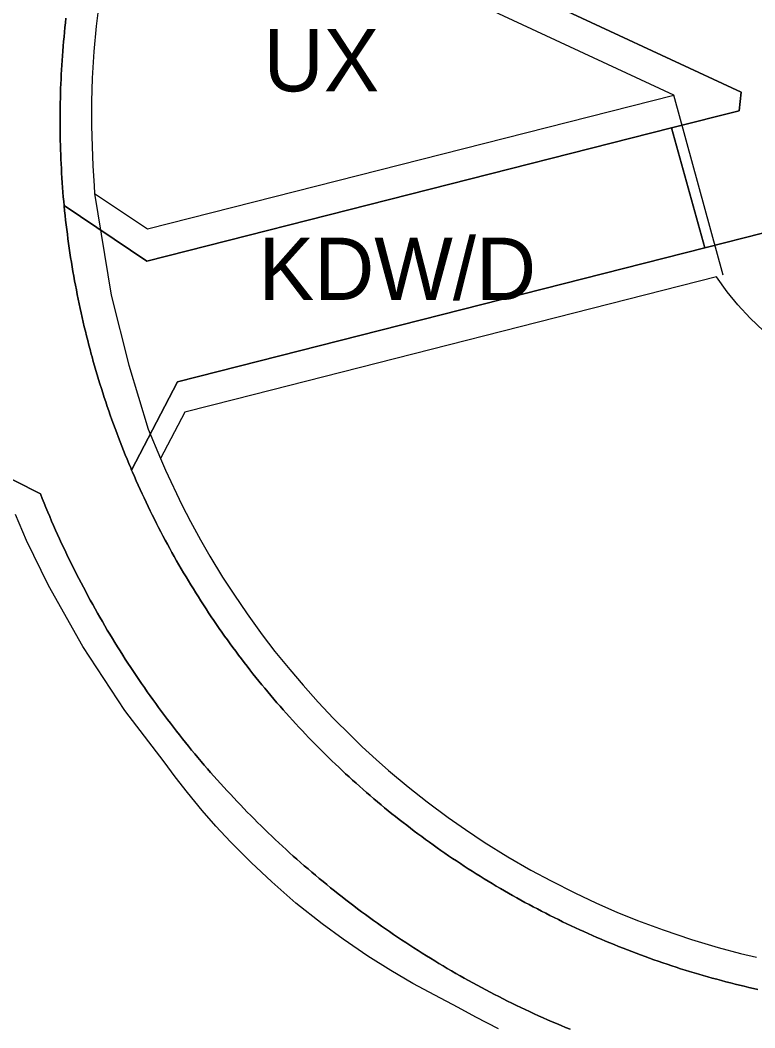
# Model space of a CAD drawing. Extents: x -297746 to -295403, y 27112 to 28877.
# Drawn here: x -297178.2 to -297060.2, y 27583.6 to 27745.5 of the extents above; entities that cross this region are included whole.
import ezdxf

# ---------------------------------------------------------------- set-up
doc = ezdxf.new("R2010")
doc.units = 0
for name, color, linetype in [('linie_rozgraniczajace', 7, 'Continuous'), ('linie_zabudowy_obowiazujace', 7, 'Continuous'), ('oznaczenia_przeznaczen', 7, 'Continuous')]:
    doc.layers.add(name, color=color, linetype=linetype)

msp = doc.modelspace()

# ---------------------------------------------------------------- linework, layer by layer
at = {"layer": 'linie_rozgraniczajace'}
for points in [[(-297152.791, 27775.987), (-297062.466, 27733.921), (-297062.777, 27730.939), (-297073.62, 27728.183), (-297157.907, 27706.762), (-297171.185, 27715.692), (-297171.248, 27716.366), (-297171.315, 27717.119), (-297171.378, 27717.873), (-297171.436, 27718.627), (-297171.491, 27719.381), (-297171.542, 27720.136), (-297171.589, 27720.891), (-297171.631, 27721.646), (-297171.67, 27722.401), (-297171.705, 27723.157), (-297171.736, 27723.912), (-297171.763, 27724.668), (-297171.786, 27725.424), (-297171.804, 27726.18), (-297171.819, 27726.936), (-297171.83, 27727.693), (-297171.837, 27728.449), (-297171.84, 27729.205), (-297171.838, 27729.962), (-297171.833, 27730.718), (-297171.824, 27731.474), (-297171.811, 27732.23), (-297171.794, 27732.986), (-297171.773, 27733.742), (-297171.747, 27734.498), (-297171.718, 27735.254), (-297171.685, 27736.01), (-297171.648, 27736.765), (-297171.607, 27737.52), (-297171.562, 27738.275), (-297171.513, 27739.03), (-297171.459, 27739.784), (-297171.402, 27740.538), (-297171.341, 27741.292), (-297171.276, 27742.046), (-297171.207, 27742.799), (-297171.134, 27743.552), (-297171.057, 27744.304), (-297170.976, 27745.056), (-297170.891, 27745.807)], [(-297059.011, 27711.26), (-297068.251, 27708.911), (-297073.62, 27728.183), (-297062.777, 27730.939), (-297062.466, 27733.921), (-297152.791, 27775.987)], [(-297170.891, 27745.807), (-297170.976, 27745.056), (-297171.057, 27744.304), (-297171.134, 27743.552), (-297171.207, 27742.799), (-297171.276, 27742.046), (-297171.341, 27741.292), (-297171.402, 27740.538), (-297171.459, 27739.784), (-297171.513, 27739.03), (-297171.562, 27738.275), (-297171.607, 27737.52), (-297171.648, 27736.765), (-297171.685, 27736.01), (-297171.718, 27735.254), (-297171.747, 27734.498), (-297171.773, 27733.742), (-297171.794, 27732.986), (-297171.811, 27732.23), (-297171.824, 27731.474), (-297171.833, 27730.718), (-297171.838, 27729.962), (-297171.84, 27729.205), (-297171.837, 27728.449), (-297171.83, 27727.693), (-297171.819, 27726.936), (-297171.804, 27726.18), (-297171.786, 27725.424), (-297171.763, 27724.668), (-297171.736, 27723.912), (-297171.705, 27723.157), (-297171.67, 27722.401), (-297171.631, 27721.646), (-297171.589, 27720.891), (-297171.542, 27720.136), (-297171.491, 27719.381), (-297171.436, 27718.627), (-297171.378, 27717.873), (-297171.315, 27717.119), (-297171.248, 27716.366), (-297171.185, 27715.692), (-297171.177, 27715.613), (-297171.103, 27714.86), (-297171.024, 27714.108), (-297170.941, 27713.356), (-297170.855, 27712.605), (-297170.764, 27711.854), (-297170.669, 27711.104), (-297170.571, 27710.354), (-297170.468, 27709.605), (-297170.362, 27708.856), (-297170.251, 27708.108), (-297170.137, 27707.36), (-297170.019, 27706.613), (-297169.896, 27705.867), (-297169.77, 27705.121), (-297169.64, 27704.376), (-297169.506, 27703.632), (-297169.368, 27702.888), (-297169.226, 27702.145), (-297169.08, 27701.403), (-297168.93, 27700.662), (-297168.776, 27699.921), (-297168.619, 27699.182), (-297168.457, 27698.443), (-297168.292, 27697.705), (-297168.122, 27696.968), (-297167.949, 27696.231), (-297167.772, 27695.496), (-297167.591, 27694.762), (-297167.406, 27694.029)], [(-297152.753, 27657.985), (-297153.129, 27658.642), (-297153.501, 27659.3), (-297153.87, 27659.96), (-297154.235, 27660.622), (-297154.597, 27661.287), (-297154.955, 27661.953), (-297155.31, 27662.621), (-297155.661, 27663.29), (-297156.009, 27663.962), (-297156.353, 27664.636), (-297156.693, 27665.311), (-297157.03, 27665.988), (-297157.364, 27666.667), (-297157.693, 27667.347), (-297158.02, 27668.03), (-297158.342, 27668.714), (-297158.661, 27669.4), (-297158.976, 27670.087), (-297159.288, 27670.776), (-297159.596, 27671.467), (-297159.901, 27672.159), (-297160.201, 27672.853), (-297160.351, 27673.202), (-297152.966, 27687.382), (-297068.251, 27708.911), (-297059.011, 27711.26)], [(-297167.406, 27694.029), (-297167.217, 27693.296), (-297167.024, 27692.565), (-297166.828, 27691.835), (-297166.707, 27691.393), (-297166.504, 27690.665), (-297166.298, 27689.937), (-297166.087, 27689.211), (-297165.873, 27688.485), (-297165.655, 27687.761), (-297165.433, 27687.038), (-297165.207, 27686.316), (-297164.978, 27685.596), (-297164.744, 27684.876), (-297164.507, 27684.158), (-297164.266, 27683.441), (-297164.022, 27682.726), (-297163.773, 27682.011), (-297163.521, 27681.298), (-297163.265, 27680.587), (-297163.005, 27679.877), (-297162.741, 27679.168), (-297162.474, 27678.46), (-297162.203, 27677.754), (-297161.928, 27677.05), (-297161.649, 27676.346), (-297161.367, 27675.645), (-297161.081, 27674.945), (-297160.792, 27674.246), (-297160.498, 27673.549), (-297160.351, 27673.202), (-297160.201, 27672.853), (-297159.901, 27672.159), (-297159.596, 27671.467), (-297159.288, 27670.776), (-297158.976, 27670.087), (-297158.661, 27669.4), (-297158.342, 27668.714), (-297158.02, 27668.03), (-297157.693, 27667.347), (-297157.364, 27666.667), (-297157.03, 27665.988), (-297156.693, 27665.311), (-297156.353, 27664.636), (-297156.009, 27663.962), (-297155.661, 27663.29), (-297155.31, 27662.621), (-297154.955, 27661.953), (-297154.597, 27661.287), (-297154.235, 27660.622), (-297153.87, 27659.96), (-297153.501, 27659.3), (-297153.129, 27658.642), (-297152.753, 27657.985), (-297152.374, 27657.331), (-297151.991, 27656.679), (-297151.605, 27656.028), (-297151.215, 27655.38), (-297150.822, 27654.734), (-297150.426, 27654.09), (-297150.026, 27653.448), (-297149.623, 27652.808), (-297149.216, 27652.17), (-297148.806, 27651.535), (-297148.393, 27650.901), (-297147.976, 27650.27), (-297147.556, 27649.641), (-297147.133, 27649.014), (-297146.707, 27648.39), (-297146.277, 27647.767), (-297145.843, 27647.147), (-297145.407, 27646.53), (-297144.967, 27645.914), (-297144.524, 27645.301), (-297144.078, 27644.691), (-297143.629, 27644.083), (-297143.176, 27643.477), (-297142.72, 27642.873), (-297142.261, 27642.272), (-297141.799, 27641.673), (-297141.334, 27641.077), (-297140.865, 27640.483), (-297140.394, 27639.892), (-297139.919, 27639.303), (-297139.441, 27638.717), (-297138.96, 27638.134), (-297138.476, 27637.552), (-297137.989, 27636.974), (-297137.499, 27636.398), (-297137.006, 27635.824), (-297136.509, 27635.254), (-297136.01, 27634.686), (-297135.508, 27634.12), (-297135.003, 27633.557), (-297134.495, 27632.997), (-297133.983, 27632.44), (-297133.469, 27631.885), (-297132.952, 27631.333), (-297132.432, 27630.784), (-297131.91, 27630.237)], [(-297130.211, 27607.587), (-297130.815, 27608.092), (-297131.415, 27608.6), (-297132.014, 27609.111), (-297132.609, 27609.625), (-297133.202, 27610.142), (-297133.792, 27610.662), (-297134.38, 27611.186), (-297134.965, 27611.712), (-297135.547, 27612.241), (-297136.127, 27612.773), (-297136.704, 27613.308), (-297137.278, 27613.845), (-297137.849, 27614.386), (-297138.418, 27614.93), (-297138.984, 27615.476), (-297139.547, 27616.026), (-297140.107, 27616.578), (-297140.665, 27617.133), (-297141.219, 27617.691), (-297141.771, 27618.252), (-297142.32, 27618.815), (-297142.866, 27619.382), (-297143.41, 27619.951), (-297143.95, 27620.523), (-297144.487, 27621.097), (-297145.022, 27621.675), (-297145.553, 27622.255), (-297146.082, 27622.837), (-297146.607, 27623.423), (-297147.13, 27624.011), (-297147.65, 27624.602), (-297148.166, 27625.195), (-297148.68, 27625.791), (-297149.19, 27626.39), (-297149.698, 27626.991), (-297150.202, 27627.594), (-297150.704, 27628.201), (-297151.202, 27628.81), (-297151.697, 27629.421), (-297152.189, 27630.035), (-297152.678, 27630.651), (-297153.164, 27631.27), (-297153.646, 27631.891), (-297154.126, 27632.515), (-297154.602, 27633.141), (-297155.075, 27633.77), (-297155.545, 27634.401), (-297156.012, 27635.034), (-297156.475, 27635.67), (-297156.935, 27636.308), (-297157.392, 27636.948), (-297157.846, 27637.591), (-297158.296, 27638.236), (-297158.744, 27638.884), (-297159.187, 27639.533), (-297159.628, 27640.185), (-297160.065, 27640.839), (-297160.499, 27641.495), (-297160.93, 27642.154), (-297161.357, 27642.814), (-297161.781, 27643.477), (-297162.201, 27644.142), (-297162.618, 27644.809), (-297163.032, 27645.478), (-297163.442, 27646.15), (-297163.849, 27646.823), (-297164.252, 27647.499), (-297164.652, 27648.176), (-297165.049, 27648.856), (-297165.442, 27649.537), (-297165.831, 27650.221), (-297166.218, 27650.906), (-297166.6, 27651.593), (-297166.979, 27652.283), (-297167.355, 27652.974), (-297167.727, 27653.667), (-297168.096, 27654.362), (-297168.461, 27655.059), (-297168.822, 27655.758), (-297169.18, 27656.459), (-297169.534, 27657.161), (-297169.885, 27657.865), (-297170.232, 27658.571), (-297170.576, 27659.279), (-297170.916, 27659.988), (-297171.252, 27660.7), (-297171.585, 27661.413), (-297171.914, 27662.127), (-297172.24, 27662.843), (-297172.561, 27663.561), (-297172.88, 27664.281), (-297173.194, 27665.002), (-297173.505, 27665.725), (-297173.812, 27666.449), (-297174.116, 27667.175), (-297174.416, 27667.902), (-297174.712, 27668.631), (-297175.004, 27669.361), (-297191.301, 27677.639)], [(-297191.301, 27677.639), (-297175.004, 27669.361), (-297174.712, 27668.631), (-297174.416, 27667.902), (-297174.116, 27667.175), (-297173.812, 27666.449), (-297173.505, 27665.725), (-297173.194, 27665.002), (-297172.88, 27664.281), (-297172.561, 27663.561), (-297172.24, 27662.843), (-297171.914, 27662.127), (-297171.585, 27661.413), (-297171.252, 27660.7), (-297170.916, 27659.988), (-297170.576, 27659.279), (-297170.232, 27658.571), (-297169.885, 27657.865), (-297169.534, 27657.161), (-297169.18, 27656.459), (-297168.822, 27655.758), (-297168.461, 27655.059), (-297168.096, 27654.362), (-297167.727, 27653.667), (-297167.355, 27652.974), (-297166.979, 27652.283), (-297166.6, 27651.593), (-297166.218, 27650.906), (-297165.831, 27650.221), (-297165.442, 27649.537), (-297165.049, 27648.856), (-297164.652, 27648.176), (-297164.252, 27647.499), (-297163.849, 27646.823), (-297163.442, 27646.15), (-297163.032, 27645.478), (-297162.618, 27644.809), (-297162.201, 27644.142), (-297161.781, 27643.477), (-297161.357, 27642.814), (-297160.93, 27642.154), (-297160.499, 27641.495), (-297160.065, 27640.839), (-297159.628, 27640.185), (-297159.187, 27639.533), (-297158.744, 27638.884), (-297158.296, 27638.236), (-297157.846, 27637.591), (-297157.392, 27636.948), (-297156.935, 27636.308), (-297156.475, 27635.67), (-297156.012, 27635.034), (-297155.545, 27634.401), (-297155.075, 27633.77), (-297154.602, 27633.141), (-297154.126, 27632.515), (-297153.646, 27631.891), (-297153.164, 27631.27), (-297152.678, 27630.651), (-297152.189, 27630.035), (-297151.697, 27629.421), (-297151.202, 27628.81), (-297150.704, 27628.201), (-297150.202, 27627.594), (-297149.698, 27626.991), (-297149.19, 27626.39), (-297148.68, 27625.791), (-297148.166, 27625.195), (-297147.65, 27624.602), (-297147.13, 27624.011), (-297146.607, 27623.423), (-297146.082, 27622.837), (-297145.553, 27622.255), (-297145.022, 27621.675), (-297144.487, 27621.097), (-297143.95, 27620.523), (-297143.41, 27619.951), (-297142.866, 27619.382), (-297142.32, 27618.815), (-297141.771, 27618.252), (-297141.219, 27617.691), (-297140.665, 27617.133), (-297140.107, 27616.578), (-297139.547, 27616.026), (-297138.984, 27615.476), (-297138.418, 27614.93), (-297137.849, 27614.386), (-297137.278, 27613.845), (-297136.704, 27613.308), (-297136.127, 27612.773), (-297135.547, 27612.241), (-297134.965, 27611.712)], [(-297100.464, 27605.591), (-297101.117, 27605.972), (-297101.769, 27606.356), (-297102.418, 27606.743), (-297103.066, 27607.134), (-297103.711, 27607.529), (-297104.355, 27607.926), (-297104.996, 27608.327), (-297105.635, 27608.732), (-297106.272, 27609.14), (-297106.907, 27609.551), (-297107.539, 27609.965), (-297108.17, 27610.383), (-297108.798, 27610.804), (-297109.424, 27611.229), (-297110.047, 27611.657), (-297110.669, 27612.088), (-297111.288, 27612.522), (-297111.905, 27612.96), (-297112.519, 27613.401), (-297113.131, 27613.845), (-297113.741, 27614.293), (-297114.348, 27614.743), (-297114.953, 27615.197), (-297115.556, 27615.654), (-297116.156, 27616.114), (-297116.754, 27616.578), (-297117.349, 27617.044), (-297117.942, 27617.514), (-297118.532, 27617.987), (-297119.12, 27618.463), (-297119.705, 27618.942), (-297120.288, 27619.424), (-297120.868, 27619.909), (-297121.446, 27620.397), (-297122.021, 27620.889), (-297122.593, 27621.383), (-297123.163, 27621.88), (-297123.73, 27622.381), (-297124.294, 27622.884), (-297124.856, 27623.39), (-297125.415, 27623.9), (-297125.972, 27624.412), (-297126.525, 27624.927), (-297127.076, 27625.445), (-297127.625, 27625.966), (-297128.17, 27626.49), (-297128.713, 27627.017), (-297129.253, 27627.547), (-297129.79, 27628.079), (-297130.324, 27628.614), (-297130.855, 27629.153), (-297131.384, 27629.693), (-297131.91, 27630.237), (-297132.432, 27630.784), (-297132.952, 27631.333), (-297133.469, 27631.885), (-297133.983, 27632.44), (-297134.495, 27632.997), (-297135.003, 27633.557), (-297135.508, 27634.12), (-297136.01, 27634.686), (-297136.509, 27635.254), (-297137.006, 27635.824), (-297137.499, 27636.398), (-297137.989, 27636.974), (-297138.476, 27637.552), (-297138.96, 27638.134), (-297139.441, 27638.717), (-297139.919, 27639.303), (-297140.394, 27639.892), (-297140.865, 27640.483), (-297141.334, 27641.077), (-297141.799, 27641.673), (-297142.261, 27642.272), (-297142.72, 27642.873), (-297143.176, 27643.477), (-297143.629, 27644.083), (-297144.078, 27644.691), (-297144.524, 27645.301), (-297144.967, 27645.914), (-297145.407, 27646.53), (-297145.843, 27647.147), (-297146.277, 27647.767), (-297146.707, 27648.39), (-297147.133, 27649.014), (-297147.556, 27649.641), (-297147.976, 27650.27), (-297148.393, 27650.901), (-297148.806, 27651.535), (-297149.216, 27652.17), (-297149.623, 27652.808), (-297150.026, 27653.448), (-297150.426, 27654.09), (-297150.822, 27654.734), (-297151.215, 27655.38), (-297151.605, 27656.028), (-297151.991, 27656.679), (-297152.374, 27657.331), (-297152.753, 27657.985)], [(-297131.91, 27630.237), (-297131.384, 27629.693), (-297130.855, 27629.153), (-297130.324, 27628.614), (-297129.79, 27628.079), (-297129.253, 27627.547), (-297128.713, 27627.017), (-297128.17, 27626.49), (-297127.625, 27625.966), (-297127.076, 27625.445), (-297126.525, 27624.927), (-297125.972, 27624.412), (-297125.415, 27623.9), (-297124.856, 27623.39), (-297124.294, 27622.884), (-297123.73, 27622.381), (-297123.163, 27621.88), (-297122.593, 27621.383), (-297122.021, 27620.889), (-297121.446, 27620.397), (-297120.868, 27619.909), (-297120.288, 27619.424), (-297119.705, 27618.942), (-297119.12, 27618.463), (-297118.532, 27617.987), (-297117.942, 27617.514), (-297117.349, 27617.044), (-297116.754, 27616.578), (-297116.156, 27616.114), (-297115.556, 27615.654), (-297114.953, 27615.197), (-297114.348, 27614.743), (-297113.741, 27614.293), (-297113.131, 27613.845), (-297112.519, 27613.401), (-297111.905, 27612.96), (-297111.288, 27612.522), (-297110.669, 27612.088), (-297110.047, 27611.657), (-297109.424, 27611.229), (-297108.798, 27610.804), (-297108.17, 27610.383), (-297107.539, 27609.965), (-297106.907, 27609.551), (-297106.272, 27609.14), (-297105.635, 27608.732), (-297104.996, 27608.327), (-297104.355, 27607.926), (-297103.711, 27607.529), (-297103.066, 27607.134), (-297102.418, 27606.743), (-297101.769, 27606.356), (-297101.117, 27605.972), (-297100.464, 27605.591), (-297099.808, 27605.214), (-297099.151, 27604.841), (-297098.491, 27604.471), (-297097.83, 27604.104), (-297097.166, 27603.741), (-297096.501, 27603.381), (-297095.834, 27603.025), (-297095.164, 27602.673), (-297094.493, 27602.324), (-297093.821, 27601.978), (-297093.146, 27601.636), (-297092.47, 27601.298), (-297091.791, 27600.963), (-297091.111, 27600.632), (-297090.43, 27600.305), (-297089.746, 27599.981), (-297089.061, 27599.66), (-297088.374, 27599.344), (-297087.686, 27599.031), (-297086.996, 27598.721), (-297086.304, 27598.415), (-297085.611, 27598.113), (-297084.916, 27597.815), (-297084.219, 27597.52), (-297083.521, 27597.229), (-297082.822, 27596.942), (-297082.121, 27596.658), (-297081.418, 27596.378), (-297080.714, 27596.102), (-297080.008, 27595.829), (-297079.301, 27595.561), (-297078.593, 27595.296), (-297077.883, 27595.034), (-297077.172, 27594.777), (-297076.46, 27594.523), (-297075.746, 27594.273), (-297075.031, 27594.027), (-297074.314, 27593.785), (-297073.597, 27593.546), (-297072.878, 27593.311), (-297072.158, 27593.08), (-297071.436, 27592.853), (-297070.714, 27592.63), (-297069.99, 27592.41), (-297069.265, 27592.194), (-297068.539, 27591.982)], [(-297134.965, 27611.712), (-297134.38, 27611.186), (-297133.792, 27610.662), (-297133.202, 27610.142), (-297132.609, 27609.625), (-297132.014, 27609.111), (-297131.415, 27608.6), (-297130.815, 27608.092), (-297130.211, 27607.587), (-297129.605, 27607.085), (-297128.997, 27606.587), (-297128.386, 27606.091), (-297127.773, 27605.598), (-297127.157, 27605.109), (-297126.538, 27604.623), (-297125.917, 27604.14), (-297125.294, 27603.66), (-297124.668, 27603.183), (-297124.04, 27602.709), (-297123.409, 27602.239), (-297122.776, 27601.772), (-297122.141, 27601.308), (-297121.503, 27600.847), (-297120.863, 27600.39), (-297120.221, 27599.935), (-297119.576, 27599.484), (-297118.929, 27599.037), (-297118.28, 27598.592), (-297117.628, 27598.151), (-297116.975, 27597.714), (-297116.319, 27597.279), (-297115.661, 27596.848), (-297115, 27596.42), (-297114.338, 27595.996), (-297113.673, 27595.575), (-297113.007, 27595.157), (-297112.338, 27594.743), (-297111.667, 27594.332), (-297110.994, 27593.925), (-297110.319, 27593.521), (-297109.641, 27593.12), (-297108.962, 27592.723), (-297108.281, 27592.33), (-297107.598, 27591.94), (-297106.913, 27591.553), (-297106.226, 27591.17), (-297105.537, 27590.79), (-297104.846, 27590.414), (-297104.153, 27590.041), (-297103.458, 27589.672), (-297102.761, 27589.307), (-297102.063, 27588.945), (-297101.363, 27588.586), (-297100.66, 27588.231), (-297099.956, 27587.88), (-297099.251, 27587.532), (-297098.543, 27587.188), (-297097.834, 27586.847), (-297097.123, 27586.51), (-297096.411, 27586.177), (-297095.696, 27585.847), (-297094.98, 27585.521), (-297094.263, 27585.199), (-297093.543, 27584.88), (-297092.823, 27584.565), (-297092.1, 27584.253), (-297091.376, 27583.946), (-297090.65, 27583.642), (-297089.923, 27583.341)], [(-297089.923, 27583.341), (-297090.65, 27583.642), (-297091.376, 27583.946), (-297092.1, 27584.253), (-297092.823, 27584.565), (-297093.543, 27584.88), (-297094.263, 27585.199), (-297094.98, 27585.521), (-297095.696, 27585.847), (-297096.411, 27586.177), (-297097.123, 27586.51), (-297097.834, 27586.847), (-297098.543, 27587.188), (-297099.251, 27587.532), (-297099.956, 27587.88), (-297100.66, 27588.231), (-297101.363, 27588.586), (-297102.063, 27588.945), (-297102.761, 27589.307), (-297103.458, 27589.672), (-297104.153, 27590.041), (-297104.846, 27590.414), (-297105.537, 27590.79), (-297106.226, 27591.17), (-297106.913, 27591.553), (-297107.598, 27591.94), (-297108.281, 27592.33), (-297108.962, 27592.723), (-297109.641, 27593.12), (-297110.319, 27593.521), (-297110.994, 27593.925), (-297111.667, 27594.332), (-297112.338, 27594.743), (-297113.007, 27595.157), (-297113.673, 27595.575), (-297114.338, 27595.996), (-297115, 27596.42), (-297115.661, 27596.848), (-297116.319, 27597.279), (-297116.975, 27597.714), (-297117.628, 27598.151), (-297118.28, 27598.592), (-297118.929, 27599.037), (-297119.576, 27599.484), (-297120.221, 27599.935), (-297120.863, 27600.39), (-297121.503, 27600.847), (-297122.141, 27601.308), (-297122.776, 27601.772), (-297123.409, 27602.239), (-297124.04, 27602.709), (-297124.668, 27603.183), (-297125.294, 27603.66), (-297125.917, 27604.14), (-297126.538, 27604.623), (-297127.157, 27605.109), (-297127.773, 27605.598), (-297128.386, 27606.091), (-297128.997, 27606.587), (-297129.605, 27607.085), (-297130.211, 27607.587)], [(-297059.746, 27589.741), (-297060.484, 27589.907), (-297061.221, 27590.076), (-297061.957, 27590.249), (-297062.693, 27590.426), (-297063.427, 27590.607), (-297064.16, 27590.792), (-297064.893, 27590.981), (-297065.624, 27591.173), (-297066.354, 27591.37), (-297067.084, 27591.57), (-297067.812, 27591.774), (-297068.539, 27591.982), (-297069.265, 27592.194), (-297069.99, 27592.41), (-297070.714, 27592.63), (-297071.436, 27592.853), (-297072.158, 27593.08), (-297072.878, 27593.311), (-297073.597, 27593.546), (-297074.314, 27593.785), (-297075.031, 27594.027), (-297075.746, 27594.273), (-297076.46, 27594.523), (-297077.172, 27594.777), (-297077.883, 27595.034), (-297078.593, 27595.296), (-297079.301, 27595.561), (-297080.008, 27595.829), (-297080.714, 27596.102), (-297081.418, 27596.378), (-297082.121, 27596.658), (-297082.822, 27596.942), (-297083.521, 27597.229), (-297084.219, 27597.52), (-297084.916, 27597.815), (-297085.611, 27598.113), (-297086.304, 27598.415), (-297086.996, 27598.721), (-297087.686, 27599.031), (-297088.374, 27599.344), (-297089.061, 27599.66), (-297089.746, 27599.981), (-297090.43, 27600.305), (-297091.111, 27600.632), (-297091.791, 27600.963), (-297092.47, 27601.298), (-297093.146, 27601.636), (-297093.821, 27601.978), (-297094.493, 27602.324), (-297095.164, 27602.673), (-297095.834, 27603.025), (-297096.501, 27603.381), (-297097.166, 27603.741), (-297097.83, 27604.104), (-297098.491, 27604.471), (-297099.151, 27604.841), (-297099.808, 27605.214), (-297100.464, 27605.591)], [(-297068.539, 27591.982), (-297067.812, 27591.774), (-297067.084, 27591.57), (-297066.354, 27591.37), (-297065.624, 27591.173), (-297064.893, 27590.981), (-297064.16, 27590.792), (-297063.427, 27590.607), (-297062.693, 27590.426), (-297061.957, 27590.249), (-297061.221, 27590.076), (-297060.484, 27589.907), (-297059.746, 27589.741)]]:
    msp.add_lwpolyline(points, dxfattribs=at)
msp.add_lwpolyline([(-297160.351, 27673.202), (-297160.498, 27673.549), (-297160.792, 27674.246), (-297161.081, 27674.945), (-297161.367, 27675.645), (-297161.649, 27676.346), (-297161.928, 27677.05), (-297162.203, 27677.754), (-297162.474, 27678.46), (-297162.741, 27679.168), (-297163.005, 27679.877), (-297163.265, 27680.587), (-297163.521, 27681.298), (-297163.773, 27682.011), (-297164.022, 27682.726), (-297164.266, 27683.441), (-297164.507, 27684.158), (-297164.744, 27684.876), (-297164.978, 27685.596), (-297165.207, 27686.316), (-297165.433, 27687.038), (-297165.655, 27687.761), (-297165.873, 27688.485), (-297166.087, 27689.211), (-297166.298, 27689.937), (-297166.504, 27690.665), (-297166.707, 27691.393), (-297166.828, 27691.835), (-297167.024, 27692.565), (-297167.217, 27693.296), (-297167.406, 27694.029), (-297167.591, 27694.762), (-297167.772, 27695.496), (-297167.949, 27696.231), (-297168.122, 27696.968), (-297168.292, 27697.705), (-297168.457, 27698.443), (-297168.619, 27699.182), (-297168.776, 27699.921), (-297168.93, 27700.662), (-297169.08, 27701.403), (-297169.226, 27702.145), (-297169.368, 27702.888), (-297169.506, 27703.632), (-297169.64, 27704.376), (-297169.77, 27705.121), (-297169.896, 27705.867), (-297170.019, 27706.613), (-297170.137, 27707.36), (-297170.251, 27708.108), (-297170.362, 27708.856), (-297170.468, 27709.605), (-297170.571, 27710.354), (-297170.669, 27711.104), (-297170.764, 27711.854), (-297170.855, 27712.605), (-297170.941, 27713.356), (-297171.024, 27714.108), (-297171.103, 27714.86), (-297171.177, 27715.613), (-297171.185, 27715.692), (-297157.907, 27706.762), (-297073.62, 27728.183), (-297068.251, 27708.911), (-297152.966, 27687.382)], close=True, dxfattribs=at)
at = {"layer": 'linie_zabudowy_obowiazujace'}
for points in [[(-297073.258, 27733.435), (-297152.959, 27770.553), (-297161.552, 27767.188), (-297162.41, 27764.111), (-297163.278, 27760.652), (-297164.091, 27756.982), (-297164.853, 27752.978), (-297165.505, 27748.842), (-297166.04, 27744.544), (-297166.418, 27740.433), (-297166.671, 27736.179), (-297166.78, 27732.429), (-297166.778, 27728.538), (-297166.686, 27725.194), (-297166.563, 27722.113), (-297166.388, 27718.856), (-297166.307, 27717.62), (-297157.809, 27711.947), (-297073.258, 27733.435)], [(-297065.336, 27704.495), (-297073.258, 27733.435)], [(-297166.307, 27717.62), (-297163.606, 27701.282), (-297160.81, 27690.058), (-297157.693, 27679.771), (-297155.691, 27675.041)], [(-297058.856, 27695.574), (-297060.99, 27697.602), (-297062.957, 27699.729), (-297064.669, 27701.828), (-297066.387, 27704.227), (-297143.793, 27684.555), (-297151.773, 27682.527), (-297155.691, 27675.041), (-297154.894, 27673.207), (-297152.259, 27667.63), (-297150.878, 27664.943), (-297149.272, 27661.989), (-297147.772, 27659.375), (-297145.729, 27656.013), (-297143.943, 27653.242), (-297141.796, 27650.09), (-297139.359, 27646.727), (-297137.323, 27644.072), (-297134.946, 27641.132), (-297132.801, 27638.614), (-297130.361, 27635.892), (-297127.913, 27633.301), (-297125.157, 27630.538), (-297123.292, 27628.754), (-297121.06, 27626.704), (-297119.062, 27624.944), (-297115.941, 27622.327), (-297112.853, 27619.886), (-297109.488, 27617.384), (-297106.703, 27615.43), (-297103.699, 27613.434), (-297099.912, 27611.074), (-297096.218, 27608.932), (-297092.983, 27607.178), (-297089.172, 27605.252), (-297085.691, 27603.619), (-297082.399, 27602.182), (-297079.076, 27600.833), (-297074.962, 27599.3), (-297070.424, 27597.779), (-297066.141, 27596.501), (-297062.546, 27595.544), (-297059.951, 27594.917)], [(-297101.428, 27583.42), (-297105.077, 27585.293), (-297107.892, 27586.817), (-297111.67, 27588.83), (-297115.177, 27590.721), (-297118.701, 27592.772), (-297122.428, 27595.114), (-297126.389, 27597.814), (-297129.747, 27600.284), (-297133.945, 27603.628), (-297137.843, 27607.013), (-297141.171, 27610.14), (-297144.466, 27613.475), (-297146.807, 27616.006), (-297149.006, 27618.518), (-297151.386, 27621.396), (-297153.327, 27623.882), (-297155.14, 27626.327), (-297161.421, 27634.545), (-297168.205, 27644.832), (-297173.715, 27654.67), (-297177.221, 27661.902), (-297178.979, 27666.035)]]:
    msp.add_lwpolyline(points, dxfattribs=at)

# ---------------------------------------------------------------- texts
at = {"layer": 'oznaczenia_przeznaczen'}
for s, p in [('UX', (-297139.149, 27734.05)), ('KDW/D', (-297139.949, 27700.541))]:
    msp.add_text(s, height=10, dxfattribs=at).set_placement(p)

doc.saveas('drawing.dxf')
